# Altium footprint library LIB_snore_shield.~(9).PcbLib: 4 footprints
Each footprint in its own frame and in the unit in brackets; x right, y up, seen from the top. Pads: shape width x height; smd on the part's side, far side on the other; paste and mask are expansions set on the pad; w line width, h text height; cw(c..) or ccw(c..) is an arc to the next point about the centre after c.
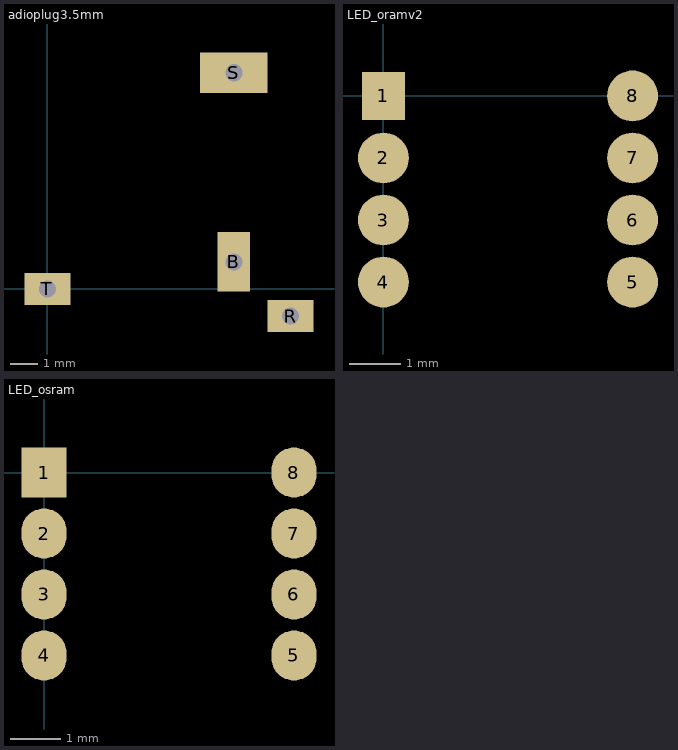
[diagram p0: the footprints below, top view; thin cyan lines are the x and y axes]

## adioplug3.5mm [mm]
pads (4):
  rect 1.2x2.2 hole 0.635 square: B(6.9,1)
  rect 1.7x1.2 / inner oval 2.54x1.27 / far side rect 1.7x1.2 hole 0.635: R(9,-1)
  rect 2.5x1.5 / inner rect 2.2x1.27 / far side rect 2.2x1.2 hole 0.635 square: S(6.9,8)
  rect 1.7x1.2 / inner rect 2.54x1.27 / far side rect 1.7x1.2 hole 0.635: T(0,0)

## LED_oramv2 [mm]
pads (8):
  rect 0.85x0.95 smd: 1(0,0)
  round 1 smd: 2(0,-1.22) 3(0,-2.44) 4(0,-3.66) 5(4.9,-3.66) 6(4.9,-2.44) 7(4.9,-1.22) 8(4.9,0)

## LED_osram [mm]
pads (8):
  rect 0.9x1 smd: 1(0,0)
  oval 0.9x1 smd: 2(0,-1.22) 3(0,-2.44) 4(0,-3.66) 5(5,-3.66) 6(5,-2.44) 7(5,-1.22) 8(5,0)

## SMD [mm]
